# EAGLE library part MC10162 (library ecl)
BINARY To 1 Of 8 Decoder (high)
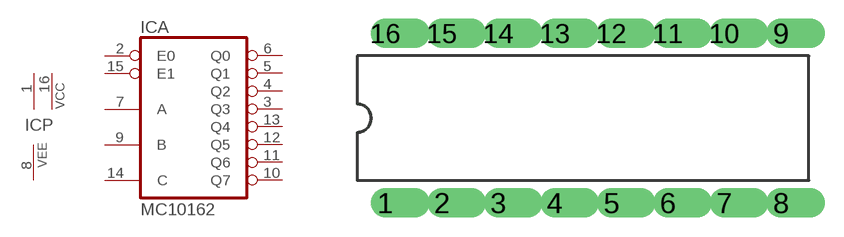
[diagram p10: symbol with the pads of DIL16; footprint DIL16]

Designator prefix IC; gates A=MC10162 P=2VCC1VEE

## MC10162  [DIL16]
1  P:VCC  pwr
2  A:E0  in
3  A:Q3  out
4  A:Q2  out
5  A:Q1  out
6  A:Q0  out
7  A:A  in
8  P:VEE  pwr
9  A:B  in
10  A:Q7  out
11  A:Q6  out
12  A:Q5  out
13  A:Q4  out
14  A:C  in
15  A:E1  in
16  P:VCC  pwr

## Footprint DIL16 (pad centres in mm)
drill 0.813 offset: 1 -8.89,-3.81; 2 -6.35,-3.81; 3 -3.81,-3.81; 4 -1.27,-3.81; 5 1.27,-3.81; 6 3.81,-3.81; 7 6.35,-3.81; 8 8.89,-3.81; 9 8.89,3.81; 10 6.35,3.81; 11 3.81,3.81; 12 1.27,3.81; 13 -1.27,3.81; 14 -3.81,3.81; 15 -6.35,3.81; 16 -8.89,3.81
